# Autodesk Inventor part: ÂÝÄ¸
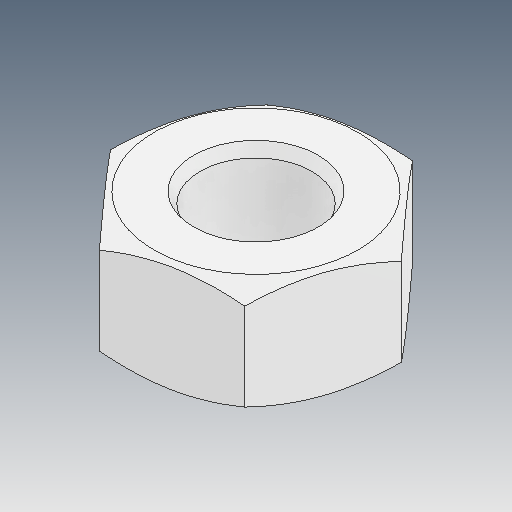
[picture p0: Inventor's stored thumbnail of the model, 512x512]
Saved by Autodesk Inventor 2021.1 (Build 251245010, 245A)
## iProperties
Created: 2021-05
Part Number: ÂÝÄ¸
Material: Ogólny
Document SubType Name: Modeling
Designer: user
Density: 1 g/cm^3
Appearance: Domyślna
Author: user
Revision Number: ÈÎºÎ
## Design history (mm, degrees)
feature "ÊäÈë1"
node "Bryła1"
